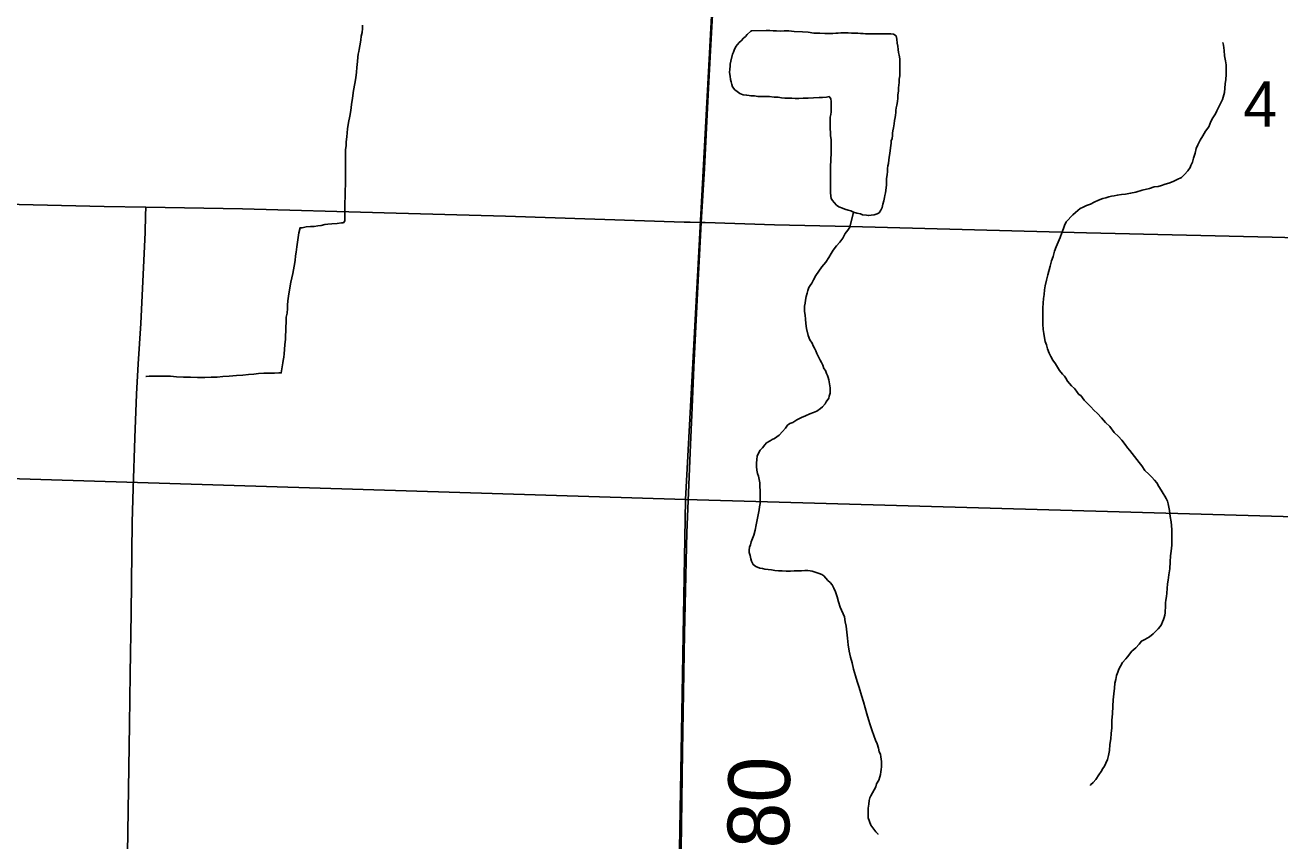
# Model space of a CAD drawing. Extents: x 1587405 to 1714697, y 1028970 to 1155083.
# Drawn here: x 1657777 to 1663879, y 1085481 to 1089450 of the extents above; entities that cross this region are included whole.
import ezdxf

# ---------------------------------------------------------------- set-up
doc = ezdxf.new("R2010")
doc.units = 0
for name, color, linetype in [('GM_X_County_Road', 7, 'Continuous'), ('GM_X_Minor_Lake', 7, 'Continuous'), ('GM_X_Minor_River', 7, 'Continuous'), ('GM_X_Section', 7, 'Continuous'), ('GM_X_Section_Text', 7, 'Continuous'), ('GM_X_Township_Road', 7, 'Continuous'), ('GM_X_Township_Road_Text', 7, 'Continuous')]:
    doc.layers.add(name, color=color, linetype=linetype)

msp = doc.modelspace()

# ---------------------------------------------------------------- linework, layer by layer
at = {"layer": 'GM_X_County_Road'}
for points in [[(1661065.2, 1088489.7), (1661080.3, 1088752), (1661099.2, 1089112.4), (1661110.2, 1089325.5), (1661126.5, 1089618.1)], [(1652987.6, 1088670.4), (1652996, 1088670.3), (1653174.8, 1088667), (1654602.3, 1088643.1), (1655947.5, 1088617.9), (1656964.6, 1088594.7), (1657194.3, 1088589.9), (1658162, 1088567), (1658364, 1088563.7)], [(1658364, 1088563.7), (1658834.2, 1088556.1), (1659523.2, 1088536.3), (1660113.6, 1088519.7), (1660982.8, 1088491.7), (1661011.1, 1088490.9), (1661065.2, 1088489.7)], [(1661065.2, 1088489.7), (1661084.9, 1088489), (1661421.7, 1088477.6), (1661789.6, 1088470.6), (1662938, 1088439.8), (1663840.5, 1088418.7), (1664693.6, 1088394.8), (1665661.5, 1088364.7), (1666317.7, 1088346.7), (1666432.5, 1088343.7)]]:
    msp.add_lwpolyline(points, dxfattribs=at)
at = {"layer": 'GM_X_Minor_Lake'}
for points in [[(1661309, 1089421.6), (1661306.1, 1089419.9), (1661288, 1089403.9), (1661280, 1089393.9), (1661269.9, 1089385.9), (1661259.9, 1089373.9), (1661249.8, 1089365.9), (1661233.7, 1089345.9), (1661225.6, 1089327.9), (1661221.6, 1089317.9), (1661217.6, 1089307.8), (1661209.5, 1089273.8), (1661205.4, 1089259.7), (1661205.4, 1089249.7), (1661203.4, 1089235.7), (1661203.3, 1089219.6), (1661205.3, 1089201.5), (1661207.3, 1089185.5), (1661211.2, 1089173.4), (1661213.2, 1089161.4), (1661217.2, 1089149.3), (1661229.2, 1089135.2), (1661239.2, 1089127.2), (1661253.3, 1089117.1), (1661269.3, 1089111), (1661285.3, 1089109), (1661297.4, 1089106.9), (1661307.4, 1089104.9), (1661323.5, 1089104.9), (1661339.5, 1089102.8), (1661357.6, 1089102.7), (1661375.6, 1089102.7), (1661395.7, 1089102.6), (1661419.8, 1089098.5), (1661439.8, 1089098.5), (1661455.9, 1089096.4), (1661471.9, 1089094.3), (1661490, 1089094.3), (1661506.1, 1089094.2), (1661522.1, 1089092.2), (1661540.2, 1089092.1), (1661560.2, 1089094.1), (1661584.3, 1089094), (1661610.4, 1089095.9), (1661638.5, 1089097.8), (1661654.6, 1089097.8), (1661674.6, 1089099.7), (1661686.7, 1089101.7), (1661694.7, 1089091.6), (1661696.7, 1089077.6), (1661696.6, 1089065.5), (1661696.6, 1089049.5), (1661696.6, 1089039.4), (1661696.6, 1089027.4), (1661694.5, 1089015.4), (1661692.5, 1089001.3), (1661692.4, 1088987.3), (1661692.4, 1088977.3), (1661692.4, 1088965.2), (1661692.4, 1088953.2), (1661692.3, 1088943.1), (1661694.3, 1088929.1), (1661694.3, 1088911), (1661696.2, 1088893), (1661696.2, 1088874.9), (1661696.2, 1088860.9), (1661696.1, 1088848.8), (1661696.1, 1088832.8), (1661696.1, 1088818.7), (1661696, 1088804.7), (1661696, 1088786.6), (1661693.9, 1088768.6), (1661693.9, 1088750.5), (1661693.9, 1088732.4), (1661693.8, 1088718.4), (1661693.8, 1088704.4), (1661693.8, 1088688.3), (1661693.7, 1088676.3), (1661693.7, 1088664.2), (1661693.7, 1088650.2), (1661693.6, 1088636.1), (1661695.6, 1088618.1), (1661697.6, 1088606), (1661703.6, 1088596), (1661711.6, 1088585.9), (1661723.6, 1088573.8), (1661733.6, 1088565.8), (1661751.7, 1088559.7), (1661763.7, 1088553.6), (1661779.7, 1088549.6), (1661791.8, 1088545.5), (1661805.8, 1088539.5), (1661821.9, 1088535.4), (1661839.9, 1088531.3), (1661849.9, 1088527.3), (1661868, 1088525.2), (1661878, 1088523.2), (1661892.1, 1088525.1), (1661906.1, 1088527.1), (1661920.2, 1088531.1)], [(1661920.2, 1088531.1), (1661930.2, 1088537.1), (1661938.3, 1088549.1), (1661944.3, 1088563.1), (1661948.4, 1088579.1), (1661952.4, 1088595.2), (1661956.5, 1088611.2), (1661958.5, 1088621.2), (1661960.5, 1088633.3), (1661964.6, 1088657.3), (1661966.7, 1088673.4), (1661966.7, 1088687.4), (1661966.7, 1088703.5), (1661968.8, 1088721.5), (1661970.8, 1088737.6), (1661970.9, 1088751.6), (1661972.9, 1088765.7), (1661974.9, 1088775.7), (1661977, 1088793.8), (1661983.1, 1088837.9), (1661985.1, 1088851.9), (1661987.2, 1088863.9), (1661989.2, 1088876), (1661989.2, 1088886), (1661993.3, 1088898.1), (1661995.3, 1088912.1), (1661995.3, 1088924.1), (1661997.4, 1088936.2), (1661999.4, 1088950.2), (1662003.5, 1088970.2), (1662005.5, 1088986.3), (1662007.5, 1089000.3), (1662009.6, 1089012.4), (1662011.6, 1089024.4), (1662011.6, 1089034.4), (1662013.7, 1089046.5), (1662015.7, 1089060.5), (1662019.8, 1089078.6), (1662021.8, 1089094.6), (1662021.8, 1089110.6), (1662023.9, 1089128.7), (1662023.9, 1089144.8), (1662026, 1089156.8), (1662028, 1089170.8), (1662028, 1089186.9), (1662030.1, 1089202.9), (1662030.1, 1089219), (1662030.1, 1089233), (1662030.2, 1089247.1), (1662030.2, 1089261.1), (1662030.2, 1089273.2), (1662030.3, 1089285.2), (1662028.3, 1089303.3), (1662024.3, 1089317.3), (1662022.3, 1089331.4), (1662020.4, 1089347.4), (1662018.4, 1089361.5), (1662016.5, 1089381.6), (1662012.5, 1089397.6), (1662000.4, 1089405.7), (1661986.4, 1089407.7), (1661970.4, 1089407.8), (1661960.3, 1089407.8), (1661948.3, 1089407.9), (1661930.2, 1089407.9), (1661918.2, 1089407.9), (1661908.1, 1089408), (1661896.1, 1089408), (1661886.1, 1089408.1), (1661876, 1089408.1), (1661864, 1089408.1), (1661851.9, 1089408.2), (1661839.9, 1089408.2), (1661825.9, 1089410.3), (1661811.8, 1089410.3), (1661795.8, 1089410.4), (1661779.7, 1089412.4), (1661757.6, 1089412.5), (1661743.6, 1089412.5), (1661731.5, 1089410.6), (1661719.5, 1089410.6), (1661705.4, 1089408.6), (1661687.4, 1089408.7), (1661665.3, 1089408.8), (1661641.2, 1089410.8), (1661613.1, 1089410.9), (1661585.1, 1089415), (1661557, 1089417.1), (1661516.8, 1089419.3), (1661490.8, 1089421.4), (1661468.7, 1089421.4), (1661448.6, 1089419.5), (1661430.5, 1089421.6), (1661414.5, 1089421.6), (1661398.4, 1089423.7), (1661380.4, 1089423.7), (1661309, 1089421.6)]]:
    msp.add_lwpolyline(points, dxfattribs=at)
at = {"layer": 'GM_X_Minor_River'}
for points in [[(1659417.8, 1089450), (1659417.7, 1089434), (1659415.7, 1089413.9), (1659411.6, 1089395.9), (1659409.6, 1089375.8), (1659405.5, 1089349.7), (1659401.5, 1089331.7), (1659399.4, 1089321.7), (1659397.4, 1089307.6), (1659395.4, 1089293.6), (1659393.3, 1089273.5), (1659391.2, 1089243.4), (1659389.2, 1089221.4), (1659385.1, 1089193.3), (1659381, 1089165.2), (1659374.9, 1089131.1), (1659368.8, 1089095), (1659364.7, 1089062.9), (1659360.6, 1089034.8), (1659356.6, 1089006.8), (1659350.5, 1088976.7), (1659344.4, 1088944.6), (1659342.3, 1088906.5), (1659338.2, 1088882.4), (1659338.2, 1088862.4), (1659336.1, 1088844.3), (1659336.1, 1088824.2), (1659336, 1088808.2), (1659336, 1088792.1), (1659336, 1088774.1), (1659335.9, 1088750), (1659335.9, 1088725.9), (1659335.8, 1088699.8), (1659335.7, 1088675.8), (1659333.7, 1088643.6), (1659333.6, 1088623.6), (1659333.6, 1088607.5), (1659331.5, 1088591.5), (1659331.5, 1088577.4), (1659331.5, 1088557.4), (1659331.4, 1088541.3), (1659331.4, 1088525.3), (1659331.3, 1088511.2), (1659331.3, 1088497.2), (1659325.3, 1088487.2), (1659315.2, 1088487.2), (1659295.2, 1088485.2), (1659269.1, 1088483.3), (1659249, 1088481.4), (1659234.9, 1088479.4), (1659216.9, 1088475.5), (1659200.8, 1088473.5), (1659182.7, 1088469.6), (1659164.7, 1088469.6), (1659144.6, 1088467.7), (1659124.5, 1088463.7), (1659114.5, 1088463.8), (1659108.4, 1088439.7), (1659104.3, 1088405.6), (1659098.2, 1088371.5), (1659096.2, 1088345.4), (1659092.1, 1088327.4), (1659090.1, 1088305.3), (1659086, 1088277.2), (1659079.9, 1088241.1), (1659069.7, 1088199), (1659059.6, 1088142.9), (1659055.5, 1088108.8), (1659053.4, 1088086.7), (1659053.4, 1088070.7), (1659051.3, 1088048.6), (1659047.3, 1088028.5), (1659047.2, 1088004.5), (1659045.2, 1087980.4), (1659045.1, 1087960.3), (1659043.1, 1087940.3), (1659043, 1087920.2), (1659041, 1087896.1), (1659038.9, 1087872.1), (1659036.8, 1087850), (1659034.8, 1087833.9), (1659032.8, 1087817.9), (1659030.7, 1087805.9), (1659024.6, 1087767.8), (1659022.6, 1087757.7), (1659010.5, 1087757.8), (1658990.5, 1087755.8), (1658966.4, 1087755.9), (1658938.3, 1087756), (1658912.2, 1087754.1), (1658890.1, 1087752.1), (1658864, 1087750.2), (1658835.9, 1087746.3), (1658805.8, 1087744.4), (1658769.7, 1087742.5), (1658739.6, 1087740.6), (1658711.5, 1087736.6), (1658681.4, 1087736.7), (1658651.3, 1087734.8)], [(1663601.8, 1089364.5), (1663603.8, 1089352.4), (1663607.7, 1089326.3), (1663609.7, 1089300.2), (1663613.6, 1089276.1), (1663617.6, 1089256.1), (1663617.5, 1089234), (1663617.5, 1089209.9), (1663615.4, 1089185.8), (1663613.4, 1089163.8), (1663611.3, 1089143.7), (1663609.3, 1089121.6), (1663603.2, 1089099.6), (1663599.2, 1089087.6), (1663589.1, 1089065.5), (1663581, 1089049.5), (1663572.9, 1089033.5), (1663564.9, 1089017.4), (1663552.8, 1088999.4), (1663542.7, 1088981.4), (1663532.6, 1088955.3), (1663516.5, 1088933.3), (1663504.4, 1088911.3), (1663490.3, 1088889.3), (1663480.2, 1088867.2), (1663472.2, 1088849.2), (1663466.1, 1088827.1), (1663458, 1088803.1), (1663454, 1088783), (1663445.9, 1088767), (1663441.9, 1088757), (1663431.8, 1088741), (1663415.7, 1088722.9), (1663399.6, 1088708.9), (1663379.5, 1088699), (1663359.4, 1088689), (1663339.3, 1088681.1), (1663321.3, 1088675.1), (1663303.2, 1088669.1), (1663287.1, 1088665.2), (1663267.1, 1088663.2), (1663245, 1088655.3), (1663208.8, 1088647.4), (1663178.7, 1088637.4), (1663152.6, 1088631.5), (1663128.5, 1088627.6), (1663108.4, 1088625.6), (1663088.3, 1088621.7), (1663072.3, 1088619.7), (1663060.2, 1088617.7), (1663046.2, 1088613.8), (1663032.1, 1088609.8), (1663018.1, 1088605.8), (1662996, 1088597.9), (1662975.9, 1088587.9), (1662957.8, 1088577.9), (1662937.7, 1088572), (1662921.6, 1088564), (1662907.6, 1088558), (1662895.5, 1088548), (1662885.5, 1088538), (1662871.4, 1088526), (1662839.2, 1088492), (1662831.1, 1088474), (1662827.1, 1088460), (1662819, 1088439.9), (1662810.9, 1088415.9), (1662800.8, 1088393.8), (1662790.8, 1088371.8), (1662782.7, 1088349.7), (1662776.6, 1088323.7), (1662768.5, 1088303.6), (1662762.5, 1088277.6), (1662750.3, 1088235.5), (1662744.2, 1088209.4), (1662738.2, 1088181.3), (1662734.1, 1088161.3), (1662732, 1088139.2), (1662730, 1088119.1), (1662727.9, 1088097.1), (1662725.9, 1088075), (1662725.8, 1088046.9), (1662725.7, 1088020.8), (1662725.7, 1087994.8), (1662727.6, 1087968.7), (1662731.6, 1087948.6), (1662733.6, 1087928.5), (1662737.5, 1087910.4), (1662743.5, 1087894.4), (1662749.5, 1087874.3), (1662757.5, 1087854.2), (1662765.5, 1087838.1), (1662775.5, 1087820), (1662787.5, 1087801.9), (1662797.4, 1087785.8), (1662807.4, 1087769.8), (1662821.5, 1087751.6), (1662831.5, 1087741.6), (1662837.5, 1087731.5), (1662845.5, 1087717.5), (1662855.5, 1087705.4)], [(1661805.8, 1088539.5), (1661787.6, 1088467.3), (1661777.5, 1088451.3), (1661765.4, 1088435.2), (1661753.3, 1088413.2), (1661739.2, 1088393.2), (1661723.2, 1088375.2), (1661707.1, 1088355.2), (1661697, 1088339.1), (1661684.9, 1088319.1), (1661670.8, 1088297.1), (1661650.7, 1088273.1), (1661636.6, 1088253.1), (1661622.5, 1088231), (1661610.4, 1088211), (1661602.3, 1088195), (1661594.3, 1088183), (1661588.2, 1088172.9), (1661584.2, 1088158.9), (1661580.1, 1088144.9), (1661576.1, 1088128.8), (1661572, 1088110.8), (1661570, 1088096.8), (1661568, 1088082.7), (1661567.9, 1088070.7), (1661567.9, 1088056.6), (1661569.9, 1088038.6), (1661571.8, 1088018.5), (1661573.8, 1087998.4), (1661577.7, 1087974.3), (1661585.7, 1087940.2), (1661593.7, 1087918.1), (1661603.7, 1087902), (1661609.7, 1087889.9), (1661615.6, 1087877.9), (1661621.6, 1087865.8), (1661627.6, 1087851.8), (1661635.6, 1087835.7), (1661643.6, 1087819.6), (1661649.6, 1087807.6), (1661655.6, 1087795.5), (1661661.6, 1087779.4), (1661669.6, 1087769.4), (1661673.6, 1087755.3), (1661679.6, 1087745.2), (1661681.5, 1087735.2), (1661685.5, 1087723.2), (1661691.5, 1087685), (1661691.4, 1087673), (1661691.4, 1087658.9), (1661687.4, 1087644.9), (1661685.3, 1087634.9), (1661673.3, 1087616.9), (1661667.2, 1087606.8), (1661655.1, 1087592.8), (1661645.1, 1087584.8), (1661627, 1087570.8), (1661610.9, 1087564.9), (1661592.8, 1087558.9), (1661572.8, 1087548.9), (1661552.7, 1087541), (1661530.6, 1087529), (1661510.5, 1087517.1), (1661496.4, 1087511.1), (1661484.3, 1087503.1), (1661474.3, 1087489.1), (1661460.2, 1087473.1), (1661444.1, 1087455.1), (1661422, 1087439.1), (1661409.9, 1087433.1), (1661399.9, 1087427.1), (1661381.8, 1087417.1), (1661373.8, 1087407.1), (1661363.7, 1087393.1), (1661351.6, 1087381.1), (1661343.6, 1087367.1), (1661337.5, 1087353.1), (1661335.5, 1087337), (1661333.4, 1087319), (1661333.4, 1087302.9), (1661335.3, 1087284.8), (1661339.3, 1087268.8), (1661343.3, 1087254.7), (1661347.3, 1087238.6), (1661349.3, 1087222.6), (1661349.2, 1087206.5), (1661351.2, 1087182.4), (1661351.1, 1087162.4), (1661351.1, 1087142.3), (1661351, 1087122.2), (1661349, 1087106.2), (1661346.9, 1087092.2), (1661332.7, 1087018), (1661326.6, 1086991.9), (1661320.6, 1086967.8), (1661314.5, 1086951.8), (1661308.5, 1086935.8), (1661304.4, 1086921.8), (1661300.4, 1086909.7), (1661298.3, 1086895.7), (1661298.3, 1086883.6)], [(1658651.3, 1087734.8), (1658615.1, 1087734.9), (1658581, 1087737.1), (1658546.9, 1087737.2), (1658512.8, 1087739.3), (1658484.7, 1087741.4), (1658454.6, 1087741.5), (1658418.5, 1087741.6), (1658396.4, 1087741.7), (1658380.4, 1087741.7), (1658366.3, 1087739.8), (1658366.3, 1087739.8), (1658364.3, 1087739.8)], [(1662855.5, 1087705.4), (1662865.5, 1087695.3), (1662879.5, 1087681.2), (1662889.5, 1087669.2), (1662901.5, 1087653.1), (1662911.5, 1087647), (1662919.5, 1087637), (1662927.5, 1087624.9), (1662959.6, 1087592.7), (1662973.6, 1087576.6), (1662991.6, 1087560.5), (1663011.6, 1087538.3), (1663031.6, 1087516.2), (1663051.6, 1087496.1), (1663073.7, 1087467.9), (1663093.7, 1087447.8), (1663109.7, 1087429.7), (1663125.7, 1087409.6), (1663137.7, 1087393.5), (1663149.7, 1087379.4), (1663159.7, 1087365.3), (1663171.7, 1087351.2), (1663183.7, 1087337.1), (1663193.7, 1087321.1), (1663207.7, 1087305), (1663221.7, 1087282.8), (1663241.8, 1087264.7), (1663255.8, 1087250.6), (1663269.8, 1087236.5), (1663279.8, 1087222.4), (1663289.8, 1087204.4), (1663301.8, 1087186.3), (1663311.8, 1087170.2), (1663319.8, 1087158.1), (1663325.8, 1087146.1), (1663331.8, 1087134), (1663335.8, 1087119.9), (1663341.7, 1087087.8), (1663345.7, 1087059.7), (1663349.6, 1087033.6), (1663351.6, 1087015.6), (1663353.5, 1086993.5), (1663353.5, 1086973.4), (1663353.4, 1086951.3), (1663353.4, 1086919.2), (1663349.3, 1086891.1), (1663347.2, 1086867.1), (1663345.1, 1086839), (1663343.1, 1086804.9), (1663339, 1086774.8), (1663334.9, 1086748.7), (1663332.9, 1086730.7), (1663330.8, 1086708.6), (1663328.7, 1086686.5), (1663326.7, 1086670.5), (1663324.6, 1086652.4), (1663322.6, 1086638.4), (1663322.6, 1086626.4), (1663320.5, 1086590.2), (1663318.5, 1086578.2), (1663316.4, 1086568.2), (1663312.4, 1086558.2), (1663308.3, 1086546.1), (1663302.3, 1086534.1), (1663296.3, 1086524.1), (1663286.2, 1086512.1), (1663274.1, 1086500.1), (1663262.1, 1086488.1), (1663244, 1086474.1), (1663221.9, 1086460.1), (1663205.8, 1086452.2), (1663193.7, 1086438.2), (1663177.6, 1086420.1), (1663159.5, 1086404.1), (1663137.4, 1086376.1), (1663129.3, 1086366.1), (1663113.2, 1086348.1), (1663103.2, 1086330.1), (1663095.1, 1086316.1), (1663091.1, 1086302), (1663085, 1086286), (1663080.9, 1086265.9), (1663076.9, 1086247.9), (1663074.8, 1086223.8), (1663070.7, 1086195.8), (1663068.7, 1086167.7), (1663066.6, 1086135.6), (1663064.5, 1086099.4), (1663062.4, 1086067.4), (1663062.3, 1086031.2), (1663058.3, 1086003.2), (1663056.2, 1085977.1), (1663052.1, 1085949), (1663050, 1085920.9), (1663046, 1085896.8), (1663039.9, 1085876.8), (1663031.8, 1085858.8), (1663025.8, 1085844.8), (1663017.7, 1085832.7), (1663009.7, 1085818.7), (1662997.6, 1085802.7)], [(1661298.3, 1086883.6), (1661302.3, 1086869.6), (1661306.3, 1086853.5), (1661310.2, 1086841.5), (1661318.2, 1086825.4), (1661330.3, 1086815.3), (1661350.3, 1086807.2), (1661362.3, 1086805.2), (1661374.4, 1086803.1), (1661390.4, 1086801.1), (1661406.5, 1086799), (1661422.5, 1086797), (1661440.6, 1086794.9), (1661458.6, 1086794.8), (1661478.7, 1086792.8), (1661498.8, 1086792.7), (1661516.8, 1086794.6), (1661532.9, 1086794.6), (1661553, 1086794.5), (1661569, 1086796.5), (1661583.1, 1086796.4), (1661595.1, 1086794.4), (1661605.1, 1086792.4), (1661623.2, 1086786.3), (1661639.2, 1086782.2), (1661651.3, 1086776.2), (1661661.3, 1086770.1), (1661681.3, 1086748), (1661691.3, 1086737.9), (1661701.3, 1086725.8), (1661709.3, 1086709.8), (1661717.3, 1086691.7), (1661725.3, 1086667.6), (1661733.2, 1086643.5), (1661741.2, 1086617.4), (1661761.2, 1086571.1), (1661765.1, 1086547.1), (1661769.1, 1086525), (1661773, 1086496.9), (1661777, 1086466.8), (1661778.9, 1086434.6), (1661784.9, 1086404.5), (1661790.8, 1086374.4), (1661798.8, 1086346.3), (1661804.7, 1086316.2), (1661814.7, 1086284), (1661822.6, 1086255.9), (1661832.6, 1086227.8), (1661844.6, 1086187.6), (1661854.5, 1086157.5), (1661862.5, 1086127.4), (1661870.5, 1086099.2), (1661878.4, 1086071.1), (1661886.4, 1086045), (1661896.4, 1086016.9), (1661904.3, 1085992.8), (1661912.3, 1085970.7), (1661920.3, 1085952.6), (1661926.3, 1085932.5), (1661930.2, 1085914.5), (1661936.2, 1085902.4), (1661938.2, 1085890.3), (1661940.2, 1085878.3), (1661942.2, 1085866.2), (1661942.1, 1085854.2), (1661942.1, 1085840.2), (1661940.1, 1085828.1), (1661938, 1085816.1), (1661936, 1085804.1), (1661934, 1085792), (1661927.9, 1085776), (1661917.8, 1085758), (1661913.8, 1085743.9), (1661905.7, 1085729.9), (1661897.7, 1085713.9), (1661889.6, 1085699.9), (1661885.6, 1085689.9), (1661881.5, 1085677.8), (1661879.5, 1085659.8), (1661877.4, 1085639.7), (1661877.4, 1085623.7), (1661877.4, 1085611.6), (1661877.3, 1085593.6), (1661883.3, 1085575.5), (1661889.3, 1085557.4), (1661913.3, 1085525.2), (1661925.3, 1085513.1), (1661925.3, 1085513.1)], [(1662997.6, 1085802.7), (1662983.5, 1085778.7), (1662971.4, 1085764.6), (1662957.3, 1085752.7), (1662957.3, 1085750.6)]]:
    msp.add_lwpolyline(points, dxfattribs=at)
at = {"layer": 'GM_X_Section'}
for points in [[(1655871.3, 1092400.1), (1656039.3, 1092397.9), (1661264.4, 1092271), (1660988.4, 1087141.1), (1655606.5, 1087308.4)], [(1661264.4, 1092271), (1661358.4, 1092269.9), (1666555.8, 1092129.2), (1666401.8, 1086987.9), (1660988.4, 1087141.1)], [(1655606.5, 1087308.4), (1660988.4, 1087141.1), (1660898.6, 1081851.1), (1655510.9, 1081994.5)], [(1660988.4, 1087141.1), (1666401.8, 1086987.9), (1666261.8, 1081696.4), (1660898.6, 1081851.1)]]:
    msp.add_lwpolyline(points, close=True, dxfattribs=at)
at = {"layer": 'GM_X_Township_Road'}
for points in [[(1658262, 1084580.6), (1658272.7, 1085210.2), (1658284.6, 1086047), (1658287.8, 1086293.1), (1658292.8, 1086588.4), (1658298.3, 1087031.5), (1658302.5, 1087195.5), (1658310.9, 1087441.5), (1658318.3, 1087654.7), (1658326.9, 1087802.1), (1658340.5, 1087998.6), (1658361.7, 1088441.1), (1658363.2, 1088523.2), (1658364, 1088563.7)], [(1660951.4, 1084501.4), (1660952, 1084538), (1660962.3, 1085128.7), (1660968.1, 1085440.3), (1660974.1, 1085916.2), (1660984.4, 1086489.8), (1660995.6, 1086981.9), (1661012.8, 1087408.3), (1661020.8, 1087588.5), (1661029.3, 1087785.3), (1661047, 1088145.8), (1661063.3, 1088457.2), (1661065.2, 1088489.7)]]:
    msp.add_lwpolyline(points, dxfattribs=at)

# ---------------------------------------------------------------- texts
at = {"layer": 'GM_X_Section_Text'}
msp.add_text('4', height=221, rotation=0.00001, dxfattribs=at).set_placement((1663701.4, 1088955.5))
at = {"layer": 'GM_X_Township_Road_Text'}
msp.add_text('T-180', height=300, rotation=89.1554, dxfattribs=at).set_placement((1661483, 1084840.6))

doc.saveas('drawing.dxf')
